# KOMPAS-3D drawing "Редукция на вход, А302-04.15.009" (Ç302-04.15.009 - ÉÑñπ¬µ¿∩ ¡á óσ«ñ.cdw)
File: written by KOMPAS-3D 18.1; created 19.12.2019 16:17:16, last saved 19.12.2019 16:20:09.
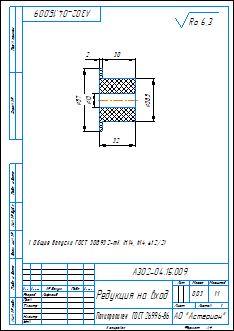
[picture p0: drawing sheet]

Sheet 1: A4, portrait

Document properties: Параметр неуказанной шероховатости: Ra 6,3; Масса: 0.0322027; Полное имя файла: А302-04.15.009 - Редукция на вход.m3d

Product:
- Part/product: Редукция на вход  | designation А302-04.15.009
    Материал: Полипропилен  ГОСТ 26996-86 (density 900 kg/m3)
    Масса: 0.0322027

Title block, sheet 1: Наименование: Редукция на вход; designation: А302-04.15.009; Материал: Полипропилен  ГОСТ 26996-86; Масса: 0,03; Количество листов документа: 1; organisation: АО "Астерион"; Форматы листов документа: A4; stored path: D:\Мембранные насосы\Мембранный электропривод\А302-00.00.000 - ASTRA-302 (МЭ200)\А302-04.00.000 - Мембранный насос ASTRA-302-PP\А302-04.15.009 - Редукция на вход.cdw; Разработал: Лифлянд

Views: Проекционный вид 3, Местный разрез 1, Справа
Referenced files in D:\Мембранные насосы\Мембранный электропривод\А302-00.00.000 - ASTRA-302 (МЭ200)\А302-04.00.000 - Мембранный насос ASTRA-302-PP\: А302-04.15.009 - Редукция на вход.m3d, А302-04.15.008 - Редукция на выход.m3d
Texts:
  Ra 6,3
Dimensions and other numbers on the sheet: 32; 57; 13; 38,5; 30; 2; 1:1; 1; 0,03

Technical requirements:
  Общие допуски ГОСТ 30893.2-mK (H14, h14,  t2/2).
